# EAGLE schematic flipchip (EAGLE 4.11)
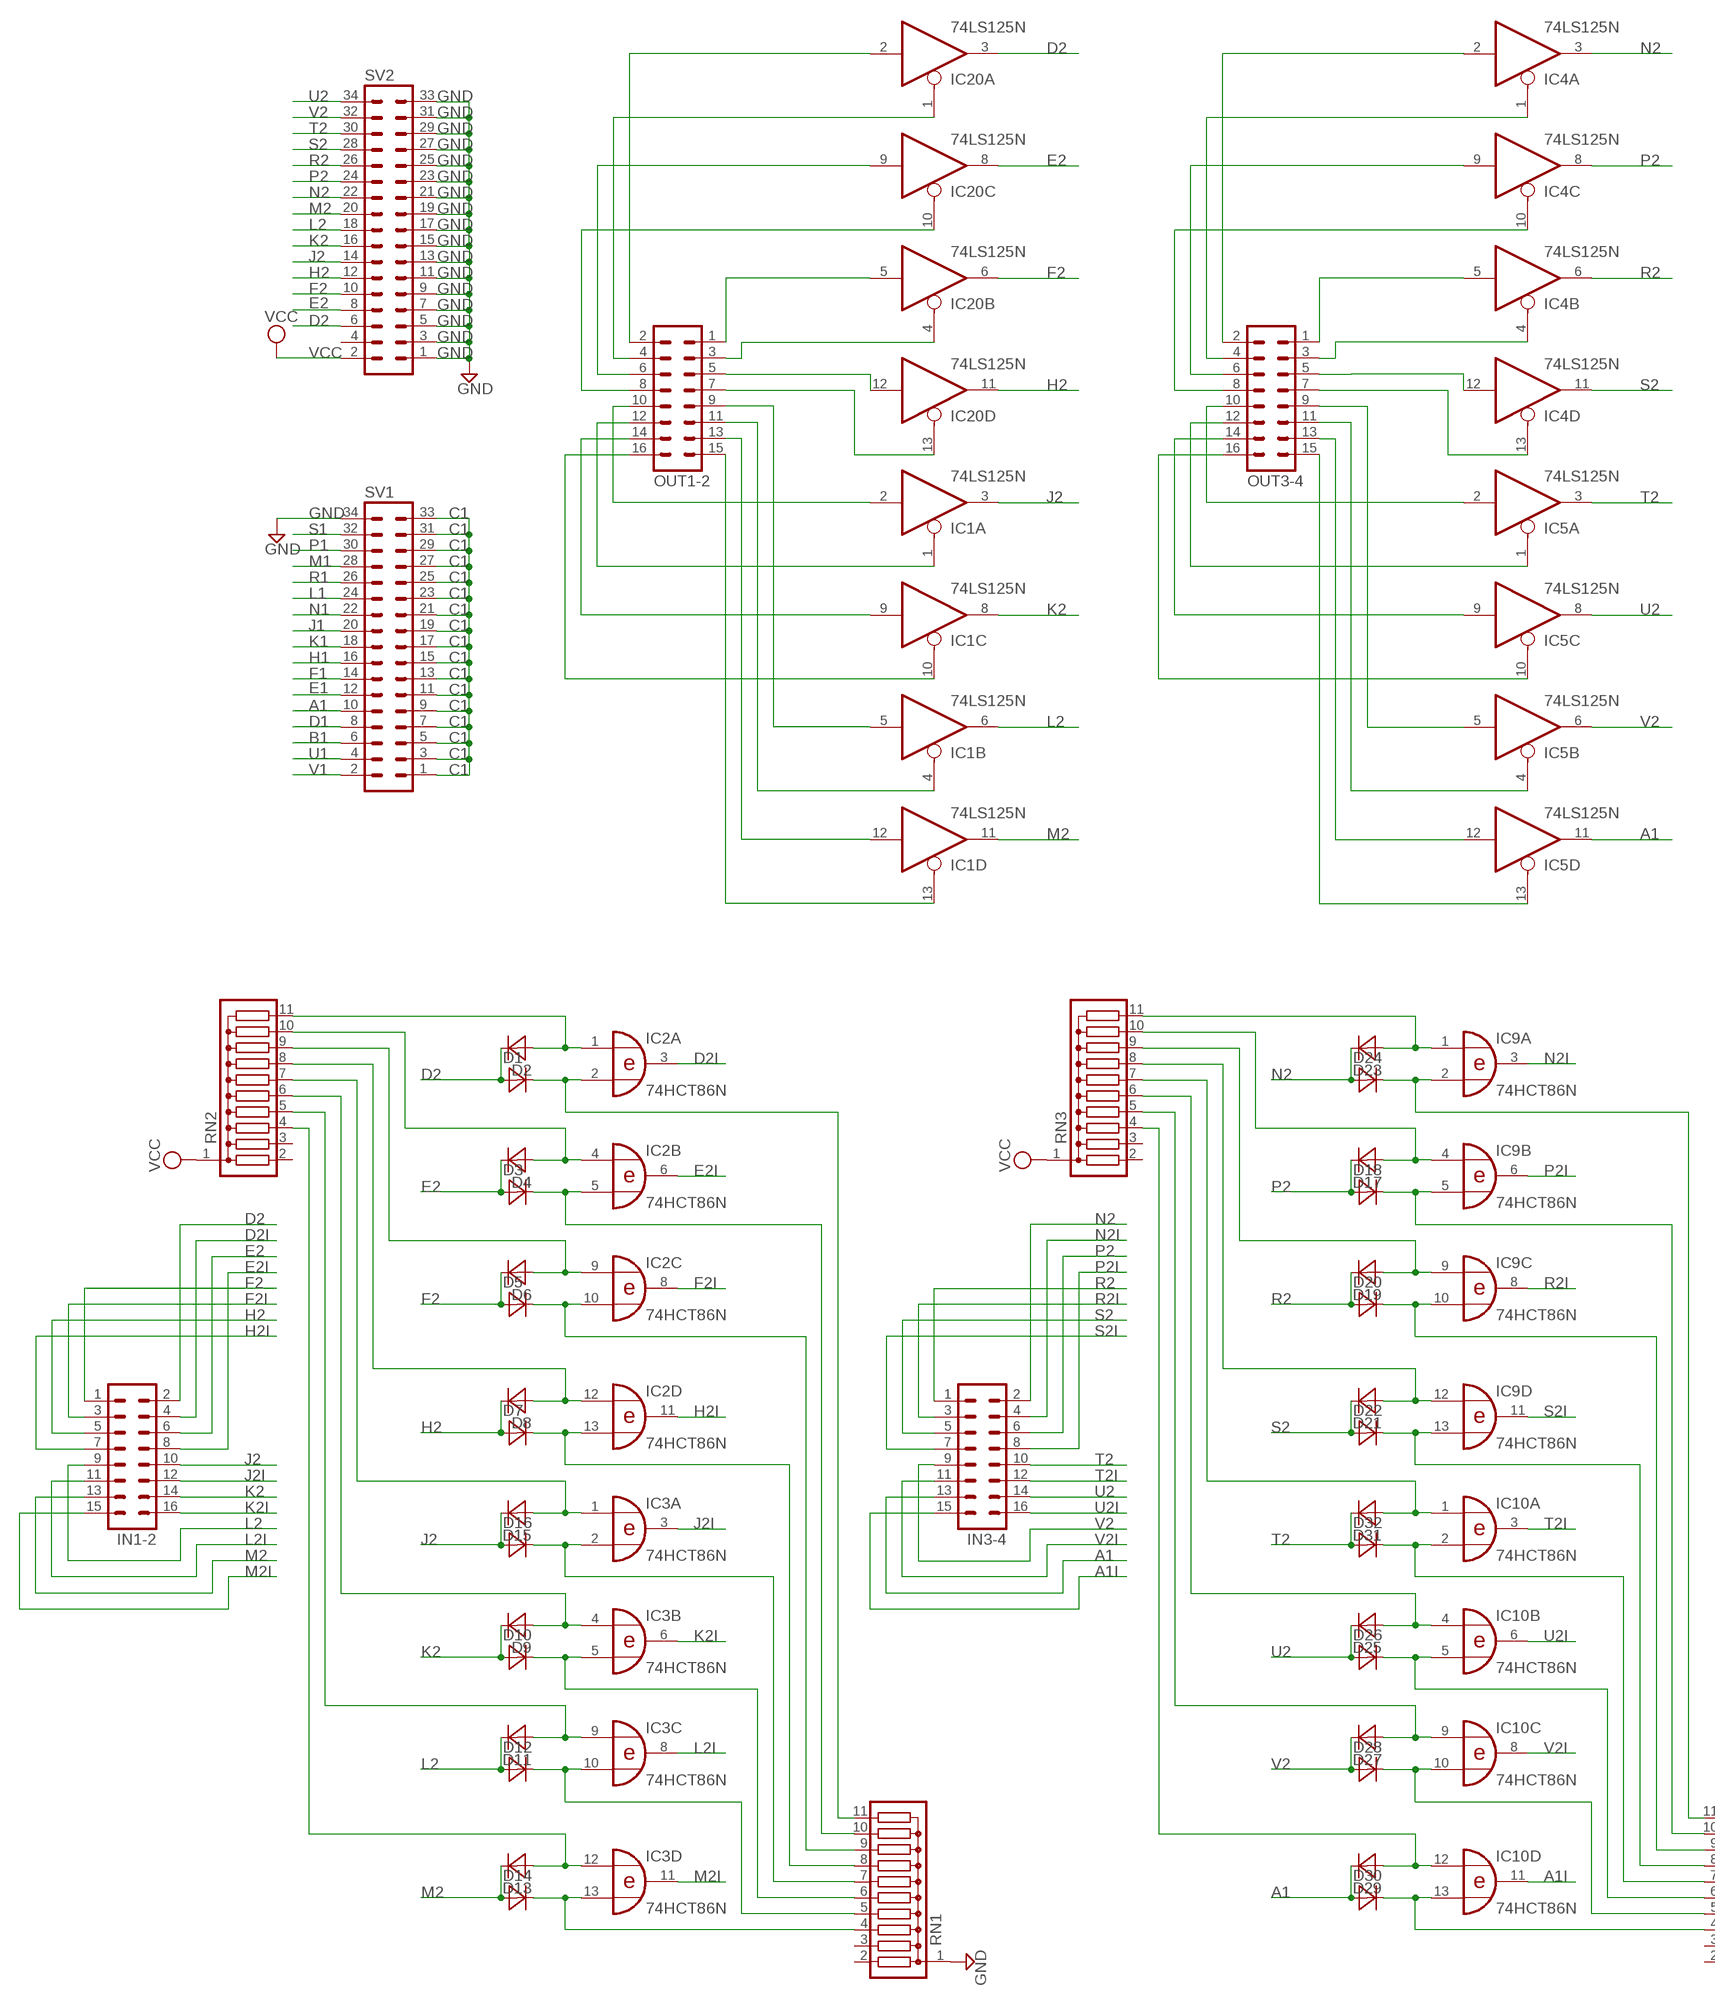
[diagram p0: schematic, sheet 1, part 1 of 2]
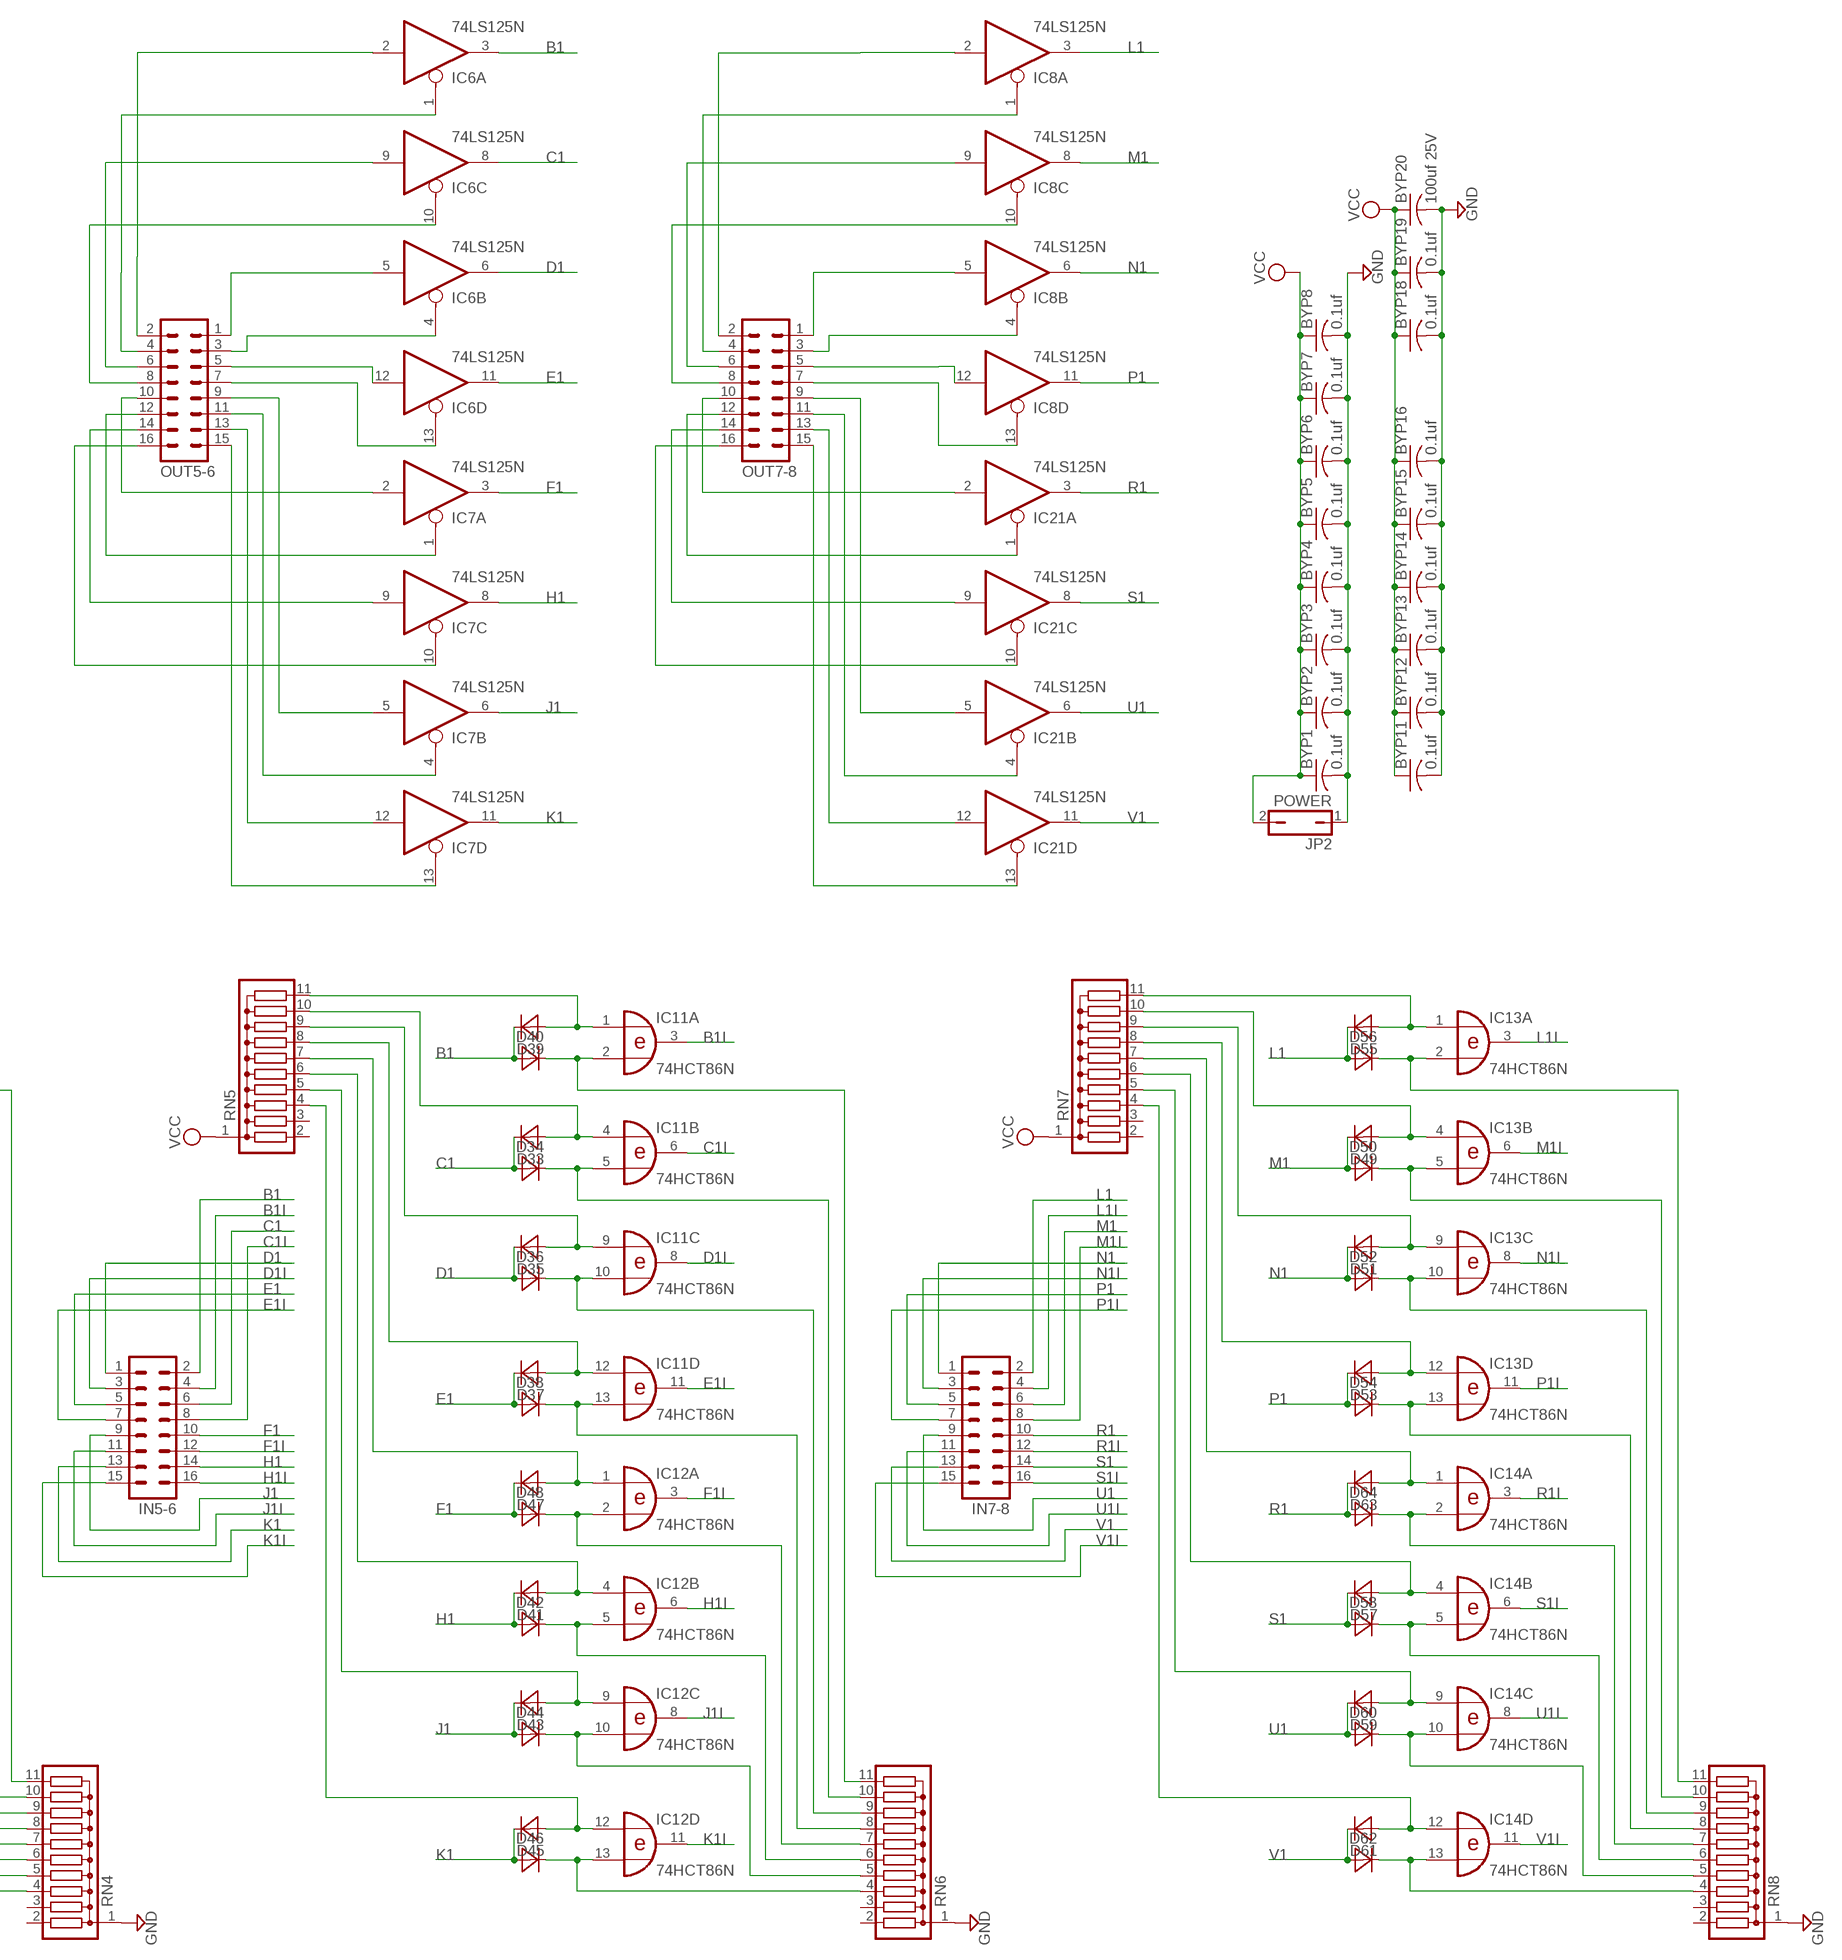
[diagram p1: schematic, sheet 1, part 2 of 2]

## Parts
BYP1  0.1uf  C-US050-025X075  [C050-025X075]
BYP2  0.1uf  C-US050-025X075  [C050-025X075]
BYP3  0.1uf  C-US050-025X075  [C050-025X075]
BYP4  0.1uf  C-US050-025X075  [C050-025X075]
BYP5  0.1uf  C-US050-025X075  [C050-025X075]
BYP6  0.1uf  C-US050-025X075  [C050-025X075]
BYP7  0.1uf  C-US050-025X075  [C050-025X075]
BYP8  0.1uf  C-US050-025X075  [C050-025X075]
BYP11  0.1uf  C-US050-025X075  [C050-025X075]
BYP12  0.1uf  C-US050-025X075  [C050-025X075]
BYP13  0.1uf  C-US050-025X075  [C050-025X075]
BYP14  0.1uf  C-US050-025X075  [C050-025X075]
BYP15  0.1uf  C-US050-025X075  [C050-025X075]
BYP16  0.1uf  C-US050-025X075  [C050-025X075]
BYP18  0.1uf  C-US050-025X075  [C050-025X075]
BYP19  0.1uf  C-US050-025X075  [C050-025X075]
BYP20  100uf 25V  C-US150-064X183  [C150-064X183]
D1  DIODE-2,5  [D-2,5]
D2  DIODE-2,5  [D-2,5]
D3  DIODE-2,5  [D-2,5]
D4  DIODE-2,5  [D-2,5]
D5  DIODE-2,5  [D-2,5]
D6  DIODE-2,5  [D-2,5]
D7  DIODE-2,5  [D-2,5]
D8  DIODE-2,5  [D-2,5]
D9  DIODE-2,5  [D-2,5]
D10  DIODE-2,5  [D-2,5]
D11  DIODE-2,5  [D-2,5]
D12  DIODE-2,5  [D-2,5]
D13  DIODE-2,5  [D-2,5]
D14  DIODE-2,5  [D-2,5]
D15  DIODE-2,5  [D-2,5]
D16  DIODE-2,5  [D-2,5]
D17  DIODE-2,5  [D-2,5]
D18  DIODE-2,5  [D-2,5]
D19  DIODE-2,5  [D-2,5]
D20  DIODE-2,5  [D-2,5]
D21  DIODE-2,5  [D-2,5]
D22  DIODE-2,5  [D-2,5]
D23  DIODE-2,5  [D-2,5]
D24  DIODE-2,5  [D-2,5]
D25  DIODE-2,5  [D-2,5]
D26  DIODE-2,5  [D-2,5]
D27  DIODE-2,5  [D-2,5]
D28  DIODE-2,5  [D-2,5]
D29  DIODE-2,5  [D-2,5]
D30  DIODE-2,5  [D-2,5]
D31  DIODE-2,5  [D-2,5]
D32  DIODE-2,5  [D-2,5]
D33  DIODE-2,5  [D-2,5]
D34  DIODE-2,5  [D-2,5]
D35  DIODE-2,5  [D-2,5]
D36  DIODE-2,5  [D-2,5]
D37  DIODE-2,5  [D-2,5]
D38  DIODE-2,5  [D-2,5]
D39  DIODE-2,5  [D-2,5]
D40  DIODE-2,5  [D-2,5]
D41  DIODE-2,5  [D-2,5]
D42  DIODE-2,5  [D-2,5]
D43  DIODE-2,5  [D-2,5]
D44  DIODE-2,5  [D-2,5]
D45  DIODE-2,5  [D-2,5]
D46  DIODE-2,5  [D-2,5]
D47  DIODE-2,5  [D-2,5]
D48  DIODE-2,5  [D-2,5]
D49  DIODE-2,5  [D-2,5]
D50  DIODE-2,5  [D-2,5]
D51  DIODE-2,5  [D-2,5]
D52  DIODE-2,5  [D-2,5]
D53  DIODE-2,5  [D-2,5]
D54  DIODE-2,5  [D-2,5]
D55  DIODE-2,5  [D-2,5]
D56  DIODE-2,5  [D-2,5]
D57  DIODE-2,5  [D-2,5]
D58  DIODE-2,5  [D-2,5]
D59  DIODE-2,5  [D-2,5]
D60  DIODE-2,5  [D-2,5]
D61  DIODE-2,5  [D-2,5]
D62  DIODE-2,5  [D-2,5]
D63  DIODE-2,5  [D-2,5]
D64  DIODE-2,5  [D-2,5]
IC1  74LS125N  [DIL14]
IC2  74HCT86N  [DIL14]
IC3  74HCT86N  [DIL14]
IC4  74LS125N  [DIL14]
IC5  74LS125N  [DIL14]
IC6  74LS125N  [DIL14]
IC7  74LS125N  [DIL14]
IC8  74LS125N  [DIL14]
IC9  74HCT86N  [DIL14]
IC10  74HCT86N  [DIL14]
IC11  74HCT86N  [DIL14]
IC12  74HCT86N  [DIL14]
IC13  74HCT86N  [DIL14]
IC14  74HCT86N  [DIL14]
IC20  74LS125N  [DIL14]
IC21  74LS125N  [DIL14]
IN1-2  MA08-2  [MA08-2]
IN3-4  MA08-2  [MA08-2]
IN5-6  MA08-2  [MA08-2]
IN7-8  MA08-2  [MA08-2]
JP2  POWER  JP1Q  [JP1]
OUT1-2  MA08-2  [MA08-2]
OUT3-4  MA08-2  [MA08-2]
OUT5-6  MA08-2  [MA08-2]
OUT7-8  MA08-2  [MA08-2]
RN1  G10R  [SIL11]
RN2  G10R  [SIL11]
RN3  G10R  [SIL11]
RN4  G10R  [SIL11]
RN5  G10R  [SIL11]
RN6  G10R  [SIL11]
RN7  G10R  [SIL11]
RN8  G10R  [SIL11]
SV1  MA17-2  [MA17-2]
SV2  MA17-2  [MA17-2]

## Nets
A1: D29.2(K) D30.1(A) IC5.11(D:O) IN3-4.13 SV1.10
A1I: IC10.11(D:O) IN3-4.15
B1: D39.2(K) D40.1(A) IC6.3(A:O) IN5-6.2 SV1.6
B1I: IC11.3(A:O) IN5-6.4
C1: D33.2(K) D34.1(A) IC6.8(C:O) IN5-6.6 SV1.1 SV1.3 SV1.5 SV1.7 SV1.9 SV1.11 SV1.13 SV1.15 SV1.17 SV1.19 SV1.21 SV1.23 SV1.25 SV1.27 SV1.29 SV1.31 SV1.33
C1I: IC11.6(B:O) IN5-6.8
D1: D35.2(K) D36.1(A) IC6.6(B:O) IN5-6.1 SV1.8
D1I: IC11.8(C:O) IN5-6.3
D2: D1.1(A) D2.2(K) IC20.3(A:O) IN1-2.2 SV2.6
D2I: IC2.3(A:O) IN1-2.4
E1: D37.2(K) D38.1(A) IC6.11(D:O) IN5-6.5 SV1.12
E1I: IC11.11(D:O) IN5-6.7
E2: D3.1(A) D4.2(K) IC20.8(C:O) IN1-2.6 SV2.8
E2I: IC2.6(B:O) IN1-2.8
F1: D47.2(K) D48.1(A) IC7.3(A:O) IN5-6.10 SV1.14
F1I: IC12.3(A:O) IN5-6.12
F2: D5.1(A) D6.2(K) IC20.6(B:O) IN1-2.1 SV2.10
F2I: IC2.8(C:O) IN1-2.3
GND [Power]: BYP1.2 BYP2.2 BYP3.2 BYP4.2 BYP5.2 BYP6.2 BYP7.2 BYP8.2 BYP11.2 BYP12.2 BYP13.2 BYP14.2 BYP15.2 BYP16.2 BYP18.2 BYP19.2 BYP20.2 JP2.1 RN1.1 RN4.1 RN6.1 RN8.1 SV1.34 SV2.1 SV2.3 SV2.5 SV2.7 SV2.9 SV2.11 SV2.13 SV2.15 SV2.17 SV2.19 SV2.21 SV2.23 SV2.25 SV2.27 SV2.29 SV2.31 SV2.33
H1: D41.2(K) D42.1(A) IC7.8(C:O) IN5-6.14 SV1.16
H1I: IC12.6(B:O) IN5-6.16
H2: D7.1(A) D8.2(K) IC20.11(D:O) IN1-2.5 SV2.12
H2I: IC2.11(D:O) IN1-2.7
J1: D43.2(K) D44.1(A) IC7.6(B:O) IN5-6.9 SV1.20
J1I: IC12.8(C:O) IN5-6.11
J2: D15.2(K) D16.1(A) IC1.3(A:O) IN1-2.10 SV2.14
J2I: IC3.3(A:O) IN1-2.12
K1: D45.2(K) D46.1(A) IC7.11(D:O) IN5-6.13 SV1.18
K1I: IC12.11(D:O) IN5-6.15
K2: D9.2(K) D10.1(A) IC1.8(C:O) IN1-2.14 SV2.16
K2I: IC3.6(B:O) IN1-2.16
L1: D55.2(K) D56.1(A) IC8.3(A:O) IN7-8.2 SV1.24
L1I: IC13.3(A:O) IN7-8.4
L2: D11.2(K) D12.1(A) IC1.6(B:O) IN1-2.9 SV2.18
L2I: IC3.8(C:O) IN1-2.11
M1: D49.2(K) D50.1(A) IC8.8(C:O) IN7-8.6 SV1.28
M1I: IC13.6(B:O) IN7-8.8
M2: D13.2(K) D14.1(A) IC1.11(D:O) IN1-2.13 SV2.20
M2I: IC3.11(D:O) IN1-2.15
N1: D51.2(K) D52.1(A) IC8.6(B:O) IN7-8.1 SV1.22
N1I: IC13.8(C:O) IN7-8.3
N2: D23.2(K) D24.1(A) IC4.3(A:O) IN3-4.2 SV2.22
N2I: IC9.3(A:O) IN3-4.4
N$1: D24.2(K) IC9.2(A:I1) RN4.11
N$2: D23.1(A) IC9.1(A:I0) RN3.11
N$3: D1.2(K) IC2.2(A:I1) RN1.11
N$4: D2.1(A) IC2.1(A:I0) RN2.11
N$5: D18.2(K) IC9.5(B:I1) RN4.10
N$6: D3.2(K) IC2.5(B:I1) RN1.10
N$7: D17.1(A) IC9.4(B:I0) RN3.10
N$8: D19.1(A) IC9.9(C:I0) RN3.9
N$9: D21.1(A) IC9.12(D:I0) RN3.8
N$10: D31.1(A) IC10.1(A:I0) RN3.7
N$11: D25.1(A) IC10.4(B:I0) RN3.6
N$12: D27.1(A) IC10.9(C:I0) RN3.5
N$13: D29.1(A) IC10.12(D:I0) RN3.4
N$14: D28.2(K) IC10.10(C:I1) RN4.5
N$15: D20.2(K) IC9.10(C:I1) RN4.9
N$16: D22.2(K) IC9.13(D:I1) RN4.8
N$17: D32.2(K) IC10.2(A:I1) RN4.7
N$18: D26.2(K) IC10.5(B:I1) RN4.6
N$19: D30.2(K) IC10.13(D:I1) RN4.4
N$20: D40.2(K) IC11.2(A:I1) RN6.11
N$21: D4.1(A) IC2.4(B:I0) RN2.10
N$22: D39.1(A) IC11.1(A:I0) RN5.11
N$23: D5.2(K) IC2.10(C:I1) RN1.9
N$24: D6.1(A) IC2.9(C:I0) RN2.9
N$25: D34.2(K) IC11.5(B:I1) RN6.10
N$26: IC6.2(A:I) OUT5-6.2
N$33: IC4.5(B:I) OUT3-4.1
N$34: IC4.4(B:OE) OUT3-4.3
N$35: IC4.12(D:I) OUT3-4.5
N$36: IC4.13(D:OE) OUT3-4.7
N$49: IC4.1(A:OE) OUT3-4.4
N$50: IC4.9(C:I) OUT3-4.6
N$51: IC4.2(A:I) OUT3-4.2
N$52: IC4.10(C:OE) OUT3-4.8
N$53: IC20.5(B:I) OUT1-2.1
N$54: IC20.4(B:OE) OUT1-2.3
N$55: IC20.12(D:I) OUT1-2.5
N$56: IC20.13(D:OE) OUT1-2.7
N$57: IC20.2(A:I) OUT1-2.2
N$58: IC20.1(A:OE) OUT1-2.4
N$59: IC20.9(C:I) OUT1-2.6
N$60: IC20.10(C:OE) OUT1-2.8
N$61: IC1.13(D:OE) OUT1-2.15
N$62: IC1.12(D:I) OUT1-2.13
N$63: IC1.4(B:OE) OUT1-2.11
N$64: IC1.5(B:I) OUT1-2.9
N$65: IC1.2(A:I) OUT1-2.10
N$66: IC1.1(A:OE) OUT1-2.12
N$67: IC1.9(C:I) OUT1-2.14
N$68: IC1.10(C:OE) OUT1-2.16
N$69: IC5.2(A:I) OUT3-4.10
N$70: IC5.1(A:OE) OUT3-4.12
N$71: IC5.9(C:I) OUT3-4.14
N$72: IC5.10(C:OE) OUT3-4.16
N$73: IC5.13(D:OE) OUT3-4.15
N$74: IC5.12(D:I) OUT3-4.13
N$75: IC5.4(B:OE) OUT3-4.11
N$76: IC5.5(B:I) OUT3-4.9
N$81: IC6.5(B:I) OUT5-6.1
N$82: IC6.4(B:OE) OUT5-6.3
N$83: IC6.12(D:I) OUT5-6.5
N$84: IC6.13(D:OE) OUT5-6.7
N$85: IC8.5(B:I) OUT7-8.1
N$86: IC8.4(B:OE) OUT7-8.3
N$87: IC8.12(D:I) OUT7-8.5
N$88: IC8.13(D:OE) OUT7-8.7
N$89: IC6.1(A:OE) OUT5-6.4
N$90: IC6.9(C:I) OUT5-6.6
N$91: IC6.10(C:OE) OUT5-6.8
N$92: IC7.5(B:I) OUT5-6.9
N$93: IC7.4(B:OE) OUT5-6.11
N$95: IC7.12(D:I) OUT5-6.13
N$96: IC7.13(D:OE) OUT5-6.15
N$97: IC7.2(A:I) OUT5-6.10
N$98: IC7.1(A:OE) OUT5-6.12
N$99: IC7.9(C:I) OUT5-6.14
N$100: IC7.10(C:OE) OUT5-6.16
N$113: IC21.13(D:OE) OUT7-8.15
N$114: IC21.12(D:I) OUT7-8.13
N$115: IC21.4(B:OE) OUT7-8.11
N$116: IC21.5(B:I) OUT7-8.9
N$117: IC21.2(A:I) OUT7-8.10
N$118: IC21.1(A:OE) OUT7-8.12
N$119: IC21.9(C:I) OUT7-8.14
N$120: IC21.10(C:OE) OUT7-8.16
N$121: IC8.10(C:OE) OUT7-8.8
N$122: IC8.9(C:I) OUT7-8.6
N$123: IC8.1(A:OE) OUT7-8.4
N$137: IC8.2(A:I) OUT7-8.2
N$138: D7.2(K) IC2.13(D:I1) RN1.8
N$139: D8.1(A) IC2.12(D:I0) RN2.8
N$140: D33.1(A) IC11.4(B:I0) RN5.10
N$141: D16.2(K) IC3.2(A:I1) RN1.7
N$142: D15.1(A) IC3.1(A:I0) RN2.7
N$143: D35.1(A) IC11.9(C:I0) RN5.9
N$144: D10.2(K) IC3.5(B:I1) RN1.6
N$145: D9.1(A) IC3.4(B:I0) RN2.6
N$146: D37.1(A) IC11.12(D:I0) RN5.8
N$147: D12.2(K) IC3.10(C:I1) RN1.5
N$148: D11.1(A) IC3.9(C:I0) RN2.5
N$149: D47.1(A) IC12.1(A:I0) RN5.7
N$150: D14.2(K) IC3.13(D:I1) RN1.4
N$151: D13.1(A) IC3.12(D:I0) RN2.4
N$152: D41.1(A) IC12.4(B:I0) RN5.6
N$153: D43.1(A) IC12.9(C:I0) RN5.5
N$154: D45.1(A) IC12.12(D:I0) RN5.4
N$155: D44.2(K) IC12.10(C:I1) RN6.5
N$156: D36.2(K) IC11.10(C:I1) RN6.9
N$157: D38.2(K) IC11.13(D:I1) RN6.8
N$158: D48.2(K) IC12.2(A:I1) RN6.7
N$159: D42.2(K) IC12.5(B:I1) RN6.6
N$160: D46.2(K) IC12.13(D:I1) RN6.4
N$161: D56.2(K) IC13.2(A:I1) RN8.11
N$162: D55.1(A) IC13.1(A:I0) RN7.11
N$163: D50.2(K) IC13.5(B:I1) RN8.10
N$164: D49.1(A) IC13.4(B:I0) RN7.10
N$165: D51.1(A) IC13.9(C:I0) RN7.9
N$166: D53.1(A) IC13.12(D:I0) RN7.8
N$167: D63.1(A) IC14.1(A:I0) RN7.7
N$168: D57.1(A) IC14.4(B:I0) RN7.6
N$169: D59.1(A) IC14.9(C:I0) RN7.5
N$170: D61.1(A) IC14.12(D:I0) RN7.4
N$171: D60.2(K) IC14.10(C:I1) RN8.5
N$172: D52.2(K) IC13.10(C:I1) RN8.9
N$173: D54.2(K) IC13.13(D:I1) RN8.8
N$174: D64.2(K) IC14.2(A:I1) RN8.7
N$175: D58.2(K) IC14.5(B:I1) RN8.6
N$176: D62.2(K) IC14.13(D:I1) RN8.4
P1: D53.2(K) D54.1(A) IC8.11(D:O) IN7-8.5 SV1.30
P1I: IC13.11(D:O) IN7-8.7
P2: D17.2(K) D18.1(A) IC4.8(C:O) IN3-4.6 SV2.24
P2I: IC9.6(B:O) IN3-4.8
R1: D63.2(K) D64.1(A) IC21.3(A:O) IN7-8.10 SV1.26
R1I: IC14.3(A:O) IN7-8.12
R2: D19.2(K) D20.1(A) IC4.6(B:O) IN3-4.1 SV2.26
R2I: IC9.8(C:O) IN3-4.3
S1: D57.2(K) D58.1(A) IC21.8(C:O) IN7-8.14 SV1.32
S1I: IC14.6(B:O) IN7-8.16
S2: D21.2(K) D22.1(A) IC4.11(D:O) IN3-4.5 SV2.28
S2I: IC9.11(D:O) IN3-4.7
T2: D31.2(K) D32.1(A) IC5.3(A:O) IN3-4.10 SV2.30
T2I: IC10.3(A:O) IN3-4.12
U1: D59.2(K) D60.1(A) IC21.6(B:O) IN7-8.9 SV1.4
U1I: IC14.8(C:O) IN7-8.11
U2: D25.2(K) D26.1(A) IC5.8(C:O) IN3-4.14 SV2.34
U2I: IC10.6(B:O) IN3-4.16
V1: D61.2(K) D62.1(A) IC21.11(D:O) IN7-8.13 SV1.2
V1I: IC14.11(D:O) IN7-8.15
V2: D27.2(K) D28.1(A) IC5.6(B:O) IN3-4.9 SV2.32
V2I: IC10.8(C:O) IN3-4.11
VCC [Power]: BYP1.1 BYP2.1 BYP3.1 BYP4.1 BYP5.1 BYP6.1 BYP7.1 BYP8.1 BYP11.1 BYP12.1 BYP13.1 BYP14.1 BYP15.1 BYP16.1 BYP18.1 BYP19.1 BYP20.1 JP2.2 RN2.1 RN3.1 RN5.1 RN7.1 SV2.2
Unconnected: RN1.2 RN1.3 RN2.2 RN2.3 RN3.2 RN3.3 RN4.2 RN4.3 RN5.2 RN5.3 RN6.2 RN6.3 RN7.2 RN7.3 RN8.2 RN8.3 SV2.4

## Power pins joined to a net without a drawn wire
GND: IC1.7(P:GND) IC2.7(P:GND) IC3.7(P:GND) IC4.7(P:GND) IC5.7(P:GND) IC6.7(P:GND) IC7.7(P:GND) IC8.7(P:GND) IC9.7(P:GND) IC10.7(P:GND) IC11.7(P:GND) IC12.7(P:GND) IC13.7(P:GND) IC14.7(P:GND) IC20.7(P:GND) IC21.7(P:GND)
VCC: IC1.14(P:VCC) IC2.14(P:VCC) IC3.14(P:VCC) IC4.14(P:VCC) IC5.14(P:VCC) IC6.14(P:VCC) IC7.14(P:VCC) IC8.14(P:VCC) IC9.14(P:VCC) IC10.14(P:VCC) IC11.14(P:VCC) IC12.14(P:VCC) IC13.14(P:VCC) IC14.14(P:VCC) IC20.14(P:VCC) IC21.14(P:VCC)

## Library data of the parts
BYP1-BYP8 BYP11-BYP16 BYP18-BYP20 = rcl:C-US: CAPACITOR, American symbol
D1-D64 = discrete:DIODE-2,5
IC1 IC4-IC8 IC20 IC21 = 74xx-us:74*125: Quad bus BUFFER, 3-state
IC2 IC3 IC9-IC14 = 74xx-eu:74*86: Quad 2-input EXCLUSIVE-OR (XOR) gate
IN1-2 IN3-4 IN5-6 IN7-8 OUT1-2 OUT3-4 OUT5-6 OUT7-8 = con-lstb:MA08-2: PIN HEADER
JP2 = jumper:JP1Q: JUMPER
RN1-RN8 = resistor-sil:G10R: SIL RESISTOR
SV1 SV2 = con-lstb:MA17-2: PIN HEADER

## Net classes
1 Power: width 0.508 mm, drill 0.254 mm, clearance 0.254 mm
